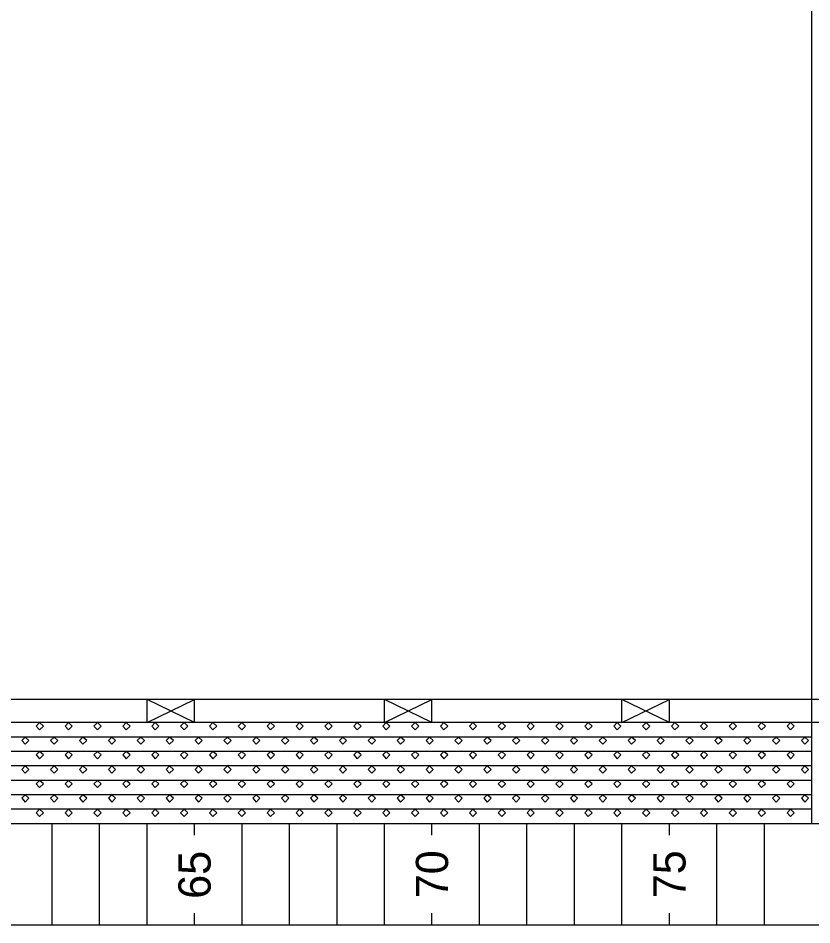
# Model space of a CAD drawing. Extents: x 1313964 to 1316843, y 2087046 to 2096619.
# Drawn here: x 1314005.66 to 1314022.37, y 2089873.43 to 2089892.52 of the extents above; entities that cross this region are included whole.
import ezdxf

# ---------------------------------------------------------------- set-up
doc = ezdxf.new("R2010")
doc.units = 0
doc.layers.add('B-Sub-Contour', color=7, linetype='Continuous')

msp = doc.modelspace()

# ---------------------------------------------------------------- linework, layer by layer
at = {"layer": 'B-Sub-Contour'}
for points in [[(1314036.804, 2089873.434), (1314036.804, 2089916.306), (1313975.385, 2089916.306), (1313975.385, 2089873.434), (1314036.804, 2089873.434)], [(1314022.372, 2089878.178), (1314022.372, 2089894.049)], [(1314034.372, 2089878.178), (1313989.372, 2089878.178)], [(1314008.372, 2089877.691), (1314009.372, 2089878.178)], [(1314009.372, 2089877.691), (1314008.372, 2089878.178)], [(1314008.372, 2089877.691), (1314008.372, 2089878.178)], [(1314009.372, 2089877.691), (1314009.372, 2089878.178)], [(1314013.372, 2089877.691), (1314014.372, 2089878.178)], [(1314014.372, 2089877.691), (1314013.372, 2089878.178)], [(1314013.372, 2089877.691), (1314013.372, 2089878.178)], [(1314014.372, 2089877.691), (1314014.372, 2089878.178)], [(1314018.372, 2089877.691), (1314019.372, 2089878.178)], [(1314019.372, 2089877.691), (1314018.372, 2089878.178)], [(1314018.372, 2089877.691), (1314018.372, 2089878.178)], [(1314019.372, 2089877.691), (1314019.372, 2089878.178)], [(1314022.372, 2089877.691), (1314022.372, 2089878.178)], [(1314034.372, 2089877.691), (1313982.683, 2089877.691)], [(1314022.372, 2089875.563), (1314022.372, 2089877.691)], [(1314022.372, 2089877.387), (1313997.372, 2089877.387)], [(1314022.372, 2089877.083), (1313997.372, 2089877.083)], [(1314022.372, 2089876.779), (1313997.372, 2089876.779)], [(1314022.372, 2089876.475), (1313997.372, 2089876.475)], [(1314022.372, 2089876.171), (1313997.372, 2089876.171)], [(1314022.372, 2089875.867), (1313997.372, 2089875.867)], [(1314034.372, 2089875.563), (1313982.683, 2089875.563)], [(1314006.372, 2089873.434), (1314006.372, 2089875.563)], [(1314006.372, 2089873.434), (1314006.372, 2089875.563)], [(1314007.372, 2089873.434), (1314007.372, 2089875.563)], [(1314008.372, 2089873.434), (1314008.372, 2089875.563)], [(1314008.372, 2089873.434), (1314008.372, 2089875.563)], [(1314009.372, 2089875.319), (1314009.372, 2089875.563)], [(1314010.372, 2089873.434), (1314010.372, 2089875.563)], [(1314010.372, 2089873.434), (1314010.372, 2089875.563)], [(1314011.372, 2089873.434), (1314011.372, 2089875.563)], [(1314012.372, 2089873.434), (1314012.372, 2089875.563)], [(1314012.372, 2089873.434), (1314012.372, 2089875.563)], [(1314013.372, 2089873.434), (1314013.372, 2089875.563)], [(1314014.372, 2089875.319), (1314014.372, 2089875.563)], [(1314014.372, 2089875.319), (1314014.372, 2089875.563)], [(1314015.372, 2089873.434), (1314015.372, 2089875.563)], [(1314016.372, 2089873.434), (1314016.372, 2089875.563)], [(1314016.372, 2089873.434), (1314016.372, 2089875.563)], [(1314017.372, 2089873.434), (1314017.372, 2089875.563)], [(1314018.372, 2089873.434), (1314018.372, 2089875.563)], [(1314018.372, 2089873.434), (1314018.372, 2089875.563)], [(1314019.372, 2089875.319), (1314019.372, 2089875.563)], [(1314020.372, 2089873.434), (1314020.372, 2089875.563)], [(1314020.372, 2089873.434), (1314020.372, 2089875.563)], [(1314021.372, 2089873.434), (1314021.372, 2089875.563)], [(1314009.372, 2089873.434), (1314009.372, 2089873.678)], [(1314014.372, 2089873.434), (1314014.372, 2089873.678)], [(1314014.372, 2089873.434), (1314014.372, 2089873.678)], [(1314019.372, 2089873.434), (1314019.372, 2089873.678)]]:
    msp.add_lwpolyline(points, dxfattribs=at)
for points in [[(1314006.11, 2089877.691), (1314006.037, 2089877.618), (1314006.11, 2089877.539), (1314006.189, 2089877.618)], [(1314006.718, 2089877.691), (1314006.645, 2089877.618), (1314006.718, 2089877.539), (1314006.797, 2089877.618)], [(1314007.326, 2089877.691), (1314007.253, 2089877.618), (1314007.326, 2089877.539), (1314007.405, 2089877.618)], [(1314007.934, 2089877.691), (1314007.862, 2089877.618), (1314007.934, 2089877.539), (1314008.014, 2089877.618)], [(1314008.543, 2089877.691), (1314008.47, 2089877.618), (1314008.543, 2089877.539), (1314008.622, 2089877.618)], [(1314009.151, 2089877.691), (1314009.078, 2089877.618), (1314009.151, 2089877.539), (1314009.23, 2089877.618)], [(1314009.759, 2089877.691), (1314009.686, 2089877.618), (1314009.759, 2089877.539), (1314009.838, 2089877.618)], [(1314010.367, 2089877.691), (1314010.294, 2089877.618), (1314010.367, 2089877.539), (1314010.446, 2089877.618)], [(1314010.975, 2089877.691), (1314010.902, 2089877.618), (1314010.975, 2089877.539), (1314011.054, 2089877.618)], [(1314011.583, 2089877.691), (1314011.51, 2089877.618), (1314011.583, 2089877.539), (1314011.662, 2089877.618)], [(1314012.191, 2089877.691), (1314012.118, 2089877.618), (1314012.191, 2089877.539), (1314012.27, 2089877.618)], [(1314012.799, 2089877.691), (1314012.726, 2089877.618), (1314012.799, 2089877.539), (1314012.878, 2089877.618)], [(1314013.407, 2089877.691), (1314013.334, 2089877.618), (1314013.407, 2089877.539), (1314013.487, 2089877.618)], [(1314014.016, 2089877.691), (1314013.943, 2089877.618), (1314014.016, 2089877.539), (1314014.095, 2089877.618)], [(1314014.624, 2089877.691), (1314014.551, 2089877.618), (1314014.624, 2089877.539), (1314014.703, 2089877.618)], [(1314015.232, 2089877.691), (1314015.159, 2089877.618), (1314015.232, 2089877.539), (1314015.311, 2089877.618)], [(1314015.84, 2089877.691), (1314015.767, 2089877.618), (1314015.84, 2089877.539), (1314015.919, 2089877.618)], [(1314016.448, 2089877.691), (1314016.375, 2089877.618), (1314016.448, 2089877.539), (1314016.527, 2089877.618)], [(1314017.056, 2089877.691), (1314016.983, 2089877.618), (1314017.056, 2089877.539), (1314017.135, 2089877.618)], [(1314017.664, 2089877.691), (1314017.591, 2089877.618), (1314017.664, 2089877.539), (1314017.743, 2089877.618)], [(1314018.272, 2089877.691), (1314018.199, 2089877.618), (1314018.272, 2089877.539), (1314018.351, 2089877.618)], [(1314018.88, 2089877.691), (1314018.807, 2089877.618), (1314018.88, 2089877.539), (1314018.959, 2089877.618)], [(1314019.489, 2089877.691), (1314019.416, 2089877.618), (1314019.489, 2089877.539), (1314019.568, 2089877.618)], [(1314020.097, 2089877.691), (1314020.024, 2089877.618), (1314020.097, 2089877.539), (1314020.176, 2089877.618)], [(1314020.705, 2089877.691), (1314020.632, 2089877.618), (1314020.705, 2089877.539), (1314020.784, 2089877.618)], [(1314021.313, 2089877.691), (1314021.24, 2089877.618), (1314021.313, 2089877.539), (1314021.392, 2089877.618)], [(1314021.921, 2089877.691), (1314021.848, 2089877.618), (1314021.921, 2089877.539), (1314022, 2089877.618)], [(1314005.806, 2089877.387), (1314005.733, 2089877.314), (1314005.806, 2089877.235), (1314005.885, 2089877.314)], [(1314006.414, 2089877.387), (1314006.341, 2089877.314), (1314006.414, 2089877.235), (1314006.493, 2089877.314)], [(1314007.022, 2089877.387), (1314006.949, 2089877.314), (1314007.022, 2089877.235), (1314007.101, 2089877.314)], [(1314007.63, 2089877.387), (1314007.557, 2089877.314), (1314007.63, 2089877.235), (1314007.71, 2089877.314)], [(1314008.239, 2089877.387), (1314008.166, 2089877.314), (1314008.239, 2089877.235), (1314008.318, 2089877.314)], [(1314008.847, 2089877.387), (1314008.774, 2089877.314), (1314008.847, 2089877.235), (1314008.926, 2089877.314)], [(1314009.455, 2089877.387), (1314009.382, 2089877.314), (1314009.455, 2089877.235), (1314009.534, 2089877.314)], [(1314010.063, 2089877.387), (1314009.99, 2089877.314), (1314010.063, 2089877.235), (1314010.142, 2089877.314)], [(1314010.671, 2089877.387), (1314010.598, 2089877.314), (1314010.671, 2089877.235), (1314010.75, 2089877.314)], [(1314011.279, 2089877.387), (1314011.206, 2089877.314), (1314011.279, 2089877.235), (1314011.358, 2089877.314)], [(1314011.887, 2089877.387), (1314011.814, 2089877.314), (1314011.887, 2089877.235), (1314011.966, 2089877.314)], [(1314012.495, 2089877.387), (1314012.422, 2089877.314), (1314012.495, 2089877.235), (1314012.574, 2089877.314)], [(1314013.103, 2089877.387), (1314013.03, 2089877.314), (1314013.103, 2089877.235), (1314013.182, 2089877.314)], [(1314013.712, 2089877.387), (1314013.639, 2089877.314), (1314013.712, 2089877.235), (1314013.791, 2089877.314)], [(1314014.32, 2089877.387), (1314014.247, 2089877.314), (1314014.32, 2089877.235), (1314014.399, 2089877.314)], [(1314014.928, 2089877.387), (1314014.855, 2089877.314), (1314014.928, 2089877.235), (1314015.007, 2089877.314)], [(1314015.536, 2089877.387), (1314015.463, 2089877.314), (1314015.536, 2089877.235), (1314015.615, 2089877.314)], [(1314016.144, 2089877.387), (1314016.071, 2089877.314), (1314016.144, 2089877.235), (1314016.223, 2089877.314)], [(1314016.752, 2089877.387), (1314016.679, 2089877.314), (1314016.752, 2089877.235), (1314016.831, 2089877.314)], [(1314017.36, 2089877.387), (1314017.287, 2089877.314), (1314017.36, 2089877.235), (1314017.439, 2089877.314)], [(1314017.968, 2089877.387), (1314017.895, 2089877.314), (1314017.968, 2089877.235), (1314018.047, 2089877.314)], [(1314018.576, 2089877.387), (1314018.503, 2089877.314), (1314018.576, 2089877.235), (1314018.655, 2089877.314)], [(1314019.184, 2089877.387), (1314019.112, 2089877.314), (1314019.184, 2089877.235), (1314019.264, 2089877.314)], [(1314019.793, 2089877.387), (1314019.72, 2089877.314), (1314019.793, 2089877.235), (1314019.872, 2089877.314)], [(1314020.401, 2089877.387), (1314020.328, 2089877.314), (1314020.401, 2089877.235), (1314020.48, 2089877.314)], [(1314021.009, 2089877.387), (1314020.936, 2089877.314), (1314021.009, 2089877.235), (1314021.088, 2089877.314)], [(1314021.617, 2089877.387), (1314021.544, 2089877.314), (1314021.617, 2089877.235), (1314021.696, 2089877.314)], [(1314022.225, 2089877.387), (1314022.152, 2089877.314), (1314022.225, 2089877.235), (1314022.304, 2089877.314)], [(1314006.11, 2089877.083), (1314006.037, 2089877.01), (1314006.11, 2089876.931), (1314006.189, 2089877.01)], [(1314006.718, 2089877.083), (1314006.645, 2089877.01), (1314006.718, 2089876.931), (1314006.797, 2089877.01)], [(1314007.326, 2089877.083), (1314007.253, 2089877.01), (1314007.326, 2089876.931), (1314007.405, 2089877.01)], [(1314007.934, 2089877.083), (1314007.862, 2089877.01), (1314007.934, 2089876.931), (1314008.014, 2089877.01)], [(1314008.543, 2089877.083), (1314008.47, 2089877.01), (1314008.543, 2089876.931), (1314008.622, 2089877.01)], [(1314009.151, 2089877.083), (1314009.078, 2089877.01), (1314009.151, 2089876.931), (1314009.23, 2089877.01)], [(1314009.759, 2089877.083), (1314009.686, 2089877.01), (1314009.759, 2089876.931), (1314009.838, 2089877.01)], [(1314010.367, 2089877.083), (1314010.294, 2089877.01), (1314010.367, 2089876.931), (1314010.446, 2089877.01)], [(1314010.975, 2089877.083), (1314010.902, 2089877.01), (1314010.975, 2089876.931), (1314011.054, 2089877.01)], [(1314011.583, 2089877.083), (1314011.51, 2089877.01), (1314011.583, 2089876.931), (1314011.662, 2089877.01)], [(1314012.191, 2089877.083), (1314012.118, 2089877.01), (1314012.191, 2089876.931), (1314012.27, 2089877.01)], [(1314012.799, 2089877.083), (1314012.726, 2089877.01), (1314012.799, 2089876.931), (1314012.878, 2089877.01)], [(1314013.407, 2089877.083), (1314013.334, 2089877.01), (1314013.407, 2089876.931), (1314013.487, 2089877.01)], [(1314014.016, 2089877.083), (1314013.943, 2089877.01), (1314014.016, 2089876.931), (1314014.095, 2089877.01)], [(1314014.624, 2089877.083), (1314014.551, 2089877.01), (1314014.624, 2089876.931), (1314014.703, 2089877.01)], [(1314015.232, 2089877.083), (1314015.159, 2089877.01), (1314015.232, 2089876.931), (1314015.311, 2089877.01)], [(1314015.84, 2089877.083), (1314015.767, 2089877.01), (1314015.84, 2089876.931), (1314015.919, 2089877.01)], [(1314016.448, 2089877.083), (1314016.375, 2089877.01), (1314016.448, 2089876.931), (1314016.527, 2089877.01)], [(1314017.056, 2089877.083), (1314016.983, 2089877.01), (1314017.056, 2089876.931), (1314017.135, 2089877.01)], [(1314017.664, 2089877.083), (1314017.591, 2089877.01), (1314017.664, 2089876.931), (1314017.743, 2089877.01)], [(1314018.272, 2089877.083), (1314018.199, 2089877.01), (1314018.272, 2089876.931), (1314018.351, 2089877.01)], [(1314018.88, 2089877.083), (1314018.807, 2089877.01), (1314018.88, 2089876.931), (1314018.959, 2089877.01)], [(1314019.489, 2089877.083), (1314019.416, 2089877.01), (1314019.489, 2089876.931), (1314019.568, 2089877.01)], [(1314020.097, 2089877.083), (1314020.024, 2089877.01), (1314020.097, 2089876.931), (1314020.176, 2089877.01)], [(1314020.705, 2089877.083), (1314020.632, 2089877.01), (1314020.705, 2089876.931), (1314020.784, 2089877.01)], [(1314021.313, 2089877.083), (1314021.24, 2089877.01), (1314021.313, 2089876.931), (1314021.392, 2089877.01)], [(1314021.921, 2089877.083), (1314021.848, 2089877.01), (1314021.921, 2089876.931), (1314022, 2089877.01)], [(1314005.806, 2089876.779), (1314005.733, 2089876.706), (1314005.806, 2089876.627), (1314005.885, 2089876.706)], [(1314006.414, 2089876.779), (1314006.341, 2089876.706), (1314006.414, 2089876.627), (1314006.493, 2089876.706)], [(1314007.022, 2089876.779), (1314006.949, 2089876.706), (1314007.022, 2089876.627), (1314007.101, 2089876.706)], [(1314007.63, 2089876.779), (1314007.557, 2089876.706), (1314007.63, 2089876.627), (1314007.71, 2089876.706)], [(1314008.239, 2089876.779), (1314008.166, 2089876.706), (1314008.239, 2089876.627), (1314008.318, 2089876.706)], [(1314008.847, 2089876.779), (1314008.774, 2089876.706), (1314008.847, 2089876.627), (1314008.926, 2089876.706)], [(1314009.455, 2089876.779), (1314009.382, 2089876.706), (1314009.455, 2089876.627), (1314009.534, 2089876.706)], [(1314010.063, 2089876.779), (1314009.99, 2089876.706), (1314010.063, 2089876.627), (1314010.142, 2089876.706)], [(1314010.671, 2089876.779), (1314010.598, 2089876.706), (1314010.671, 2089876.627), (1314010.75, 2089876.706)], [(1314011.279, 2089876.779), (1314011.206, 2089876.706), (1314011.279, 2089876.627), (1314011.358, 2089876.706)], [(1314011.887, 2089876.779), (1314011.814, 2089876.706), (1314011.887, 2089876.627), (1314011.966, 2089876.706)], [(1314012.495, 2089876.779), (1314012.422, 2089876.706), (1314012.495, 2089876.627), (1314012.574, 2089876.706)], [(1314013.103, 2089876.779), (1314013.03, 2089876.706), (1314013.103, 2089876.627), (1314013.182, 2089876.706)], [(1314013.712, 2089876.779), (1314013.639, 2089876.706), (1314013.712, 2089876.627), (1314013.791, 2089876.706)], [(1314014.32, 2089876.779), (1314014.247, 2089876.706), (1314014.32, 2089876.627), (1314014.399, 2089876.706)], [(1314014.928, 2089876.779), (1314014.855, 2089876.706), (1314014.928, 2089876.627), (1314015.007, 2089876.706)], [(1314015.536, 2089876.779), (1314015.463, 2089876.706), (1314015.536, 2089876.627), (1314015.615, 2089876.706)], [(1314016.144, 2089876.779), (1314016.071, 2089876.706), (1314016.144, 2089876.627), (1314016.223, 2089876.706)], [(1314016.752, 2089876.779), (1314016.679, 2089876.706), (1314016.752, 2089876.627), (1314016.831, 2089876.706)], [(1314017.36, 2089876.779), (1314017.287, 2089876.706), (1314017.36, 2089876.627), (1314017.439, 2089876.706)], [(1314017.968, 2089876.779), (1314017.895, 2089876.706), (1314017.968, 2089876.627), (1314018.047, 2089876.706)], [(1314018.576, 2089876.779), (1314018.503, 2089876.706), (1314018.576, 2089876.627), (1314018.655, 2089876.706)], [(1314019.184, 2089876.779), (1314019.112, 2089876.706), (1314019.184, 2089876.627), (1314019.264, 2089876.706)], [(1314019.793, 2089876.779), (1314019.72, 2089876.706), (1314019.793, 2089876.627), (1314019.872, 2089876.706)], [(1314020.401, 2089876.779), (1314020.328, 2089876.706), (1314020.401, 2089876.627), (1314020.48, 2089876.706)], [(1314021.009, 2089876.779), (1314020.936, 2089876.706), (1314021.009, 2089876.627), (1314021.088, 2089876.706)], [(1314021.617, 2089876.779), (1314021.544, 2089876.706), (1314021.617, 2089876.627), (1314021.696, 2089876.706)], [(1314022.225, 2089876.779), (1314022.152, 2089876.706), (1314022.225, 2089876.627), (1314022.304, 2089876.706)], [(1314006.11, 2089876.475), (1314006.037, 2089876.402), (1314006.11, 2089876.323), (1314006.189, 2089876.402)], [(1314006.718, 2089876.475), (1314006.645, 2089876.402), (1314006.718, 2089876.323), (1314006.797, 2089876.402)], [(1314007.326, 2089876.475), (1314007.253, 2089876.402), (1314007.326, 2089876.323), (1314007.405, 2089876.402)], [(1314007.934, 2089876.475), (1314007.862, 2089876.402), (1314007.934, 2089876.323), (1314008.014, 2089876.402)], [(1314008.543, 2089876.475), (1314008.47, 2089876.402), (1314008.543, 2089876.323), (1314008.622, 2089876.402)], [(1314009.151, 2089876.475), (1314009.078, 2089876.402), (1314009.151, 2089876.323), (1314009.23, 2089876.402)], [(1314009.759, 2089876.475), (1314009.686, 2089876.402), (1314009.759, 2089876.323), (1314009.838, 2089876.402)], [(1314010.367, 2089876.475), (1314010.294, 2089876.402), (1314010.367, 2089876.323), (1314010.446, 2089876.402)], [(1314010.975, 2089876.475), (1314010.902, 2089876.402), (1314010.975, 2089876.323), (1314011.054, 2089876.402)], [(1314011.583, 2089876.475), (1314011.51, 2089876.402), (1314011.583, 2089876.323), (1314011.662, 2089876.402)], [(1314012.191, 2089876.475), (1314012.118, 2089876.402), (1314012.191, 2089876.323), (1314012.27, 2089876.402)], [(1314012.799, 2089876.475), (1314012.726, 2089876.402), (1314012.799, 2089876.323), (1314012.878, 2089876.402)], [(1314013.407, 2089876.475), (1314013.334, 2089876.402), (1314013.407, 2089876.323), (1314013.487, 2089876.402)], [(1314014.016, 2089876.475), (1314013.943, 2089876.402), (1314014.016, 2089876.323), (1314014.095, 2089876.402)], [(1314014.624, 2089876.475), (1314014.551, 2089876.402), (1314014.624, 2089876.323), (1314014.703, 2089876.402)], [(1314015.232, 2089876.475), (1314015.159, 2089876.402), (1314015.232, 2089876.323), (1314015.311, 2089876.402)], [(1314015.84, 2089876.475), (1314015.767, 2089876.402), (1314015.84, 2089876.323), (1314015.919, 2089876.402)], [(1314016.448, 2089876.475), (1314016.375, 2089876.402), (1314016.448, 2089876.323), (1314016.527, 2089876.402)], [(1314017.056, 2089876.475), (1314016.983, 2089876.402), (1314017.056, 2089876.323), (1314017.135, 2089876.402)], [(1314017.664, 2089876.475), (1314017.591, 2089876.402), (1314017.664, 2089876.323), (1314017.743, 2089876.402)], [(1314018.272, 2089876.475), (1314018.199, 2089876.402), (1314018.272, 2089876.323), (1314018.351, 2089876.402)], [(1314018.88, 2089876.475), (1314018.807, 2089876.402), (1314018.88, 2089876.323), (1314018.959, 2089876.402)], [(1314019.489, 2089876.475), (1314019.416, 2089876.402), (1314019.489, 2089876.323), (1314019.568, 2089876.402)], [(1314020.097, 2089876.475), (1314020.024, 2089876.402), (1314020.097, 2089876.323), (1314020.176, 2089876.402)], [(1314020.705, 2089876.475), (1314020.632, 2089876.402), (1314020.705, 2089876.323), (1314020.784, 2089876.402)], [(1314021.313, 2089876.475), (1314021.24, 2089876.402), (1314021.313, 2089876.323), (1314021.392, 2089876.402)], [(1314021.921, 2089876.475), (1314021.848, 2089876.402), (1314021.921, 2089876.323), (1314022, 2089876.402)], [(1314005.806, 2089876.171), (1314005.733, 2089876.098), (1314005.806, 2089876.019), (1314005.885, 2089876.098)], [(1314006.414, 2089876.171), (1314006.341, 2089876.098), (1314006.414, 2089876.019), (1314006.493, 2089876.098)], [(1314007.022, 2089876.171), (1314006.949, 2089876.098), (1314007.022, 2089876.019), (1314007.101, 2089876.098)], [(1314007.63, 2089876.171), (1314007.557, 2089876.098), (1314007.63, 2089876.019), (1314007.71, 2089876.098)], [(1314008.239, 2089876.171), (1314008.166, 2089876.098), (1314008.239, 2089876.019), (1314008.318, 2089876.098)], [(1314008.847, 2089876.171), (1314008.774, 2089876.098), (1314008.847, 2089876.019), (1314008.926, 2089876.098)], [(1314009.455, 2089876.171), (1314009.382, 2089876.098), (1314009.455, 2089876.019), (1314009.534, 2089876.098)], [(1314010.063, 2089876.171), (1314009.99, 2089876.098), (1314010.063, 2089876.019), (1314010.142, 2089876.098)], [(1314010.671, 2089876.171), (1314010.598, 2089876.098), (1314010.671, 2089876.019), (1314010.75, 2089876.098)], [(1314011.279, 2089876.171), (1314011.206, 2089876.098), (1314011.279, 2089876.019), (1314011.358, 2089876.098)], [(1314011.887, 2089876.171), (1314011.814, 2089876.098), (1314011.887, 2089876.019), (1314011.966, 2089876.098)], [(1314012.495, 2089876.171), (1314012.422, 2089876.098), (1314012.495, 2089876.019), (1314012.574, 2089876.098)], [(1314013.103, 2089876.171), (1314013.03, 2089876.098), (1314013.103, 2089876.019), (1314013.182, 2089876.098)], [(1314013.712, 2089876.171), (1314013.639, 2089876.098), (1314013.712, 2089876.019), (1314013.791, 2089876.098)], [(1314014.32, 2089876.171), (1314014.247, 2089876.098), (1314014.32, 2089876.019), (1314014.399, 2089876.098)], [(1314014.928, 2089876.171), (1314014.855, 2089876.098), (1314014.928, 2089876.019), (1314015.007, 2089876.098)], [(1314015.536, 2089876.171), (1314015.463, 2089876.098), (1314015.536, 2089876.019), (1314015.615, 2089876.098)], [(1314016.144, 2089876.171), (1314016.071, 2089876.098), (1314016.144, 2089876.019), (1314016.223, 2089876.098)], [(1314016.752, 2089876.171), (1314016.679, 2089876.098), (1314016.752, 2089876.019), (1314016.831, 2089876.098)], [(1314017.36, 2089876.171), (1314017.287, 2089876.098), (1314017.36, 2089876.019), (1314017.439, 2089876.098)], [(1314017.968, 2089876.171), (1314017.895, 2089876.098), (1314017.968, 2089876.019), (1314018.047, 2089876.098)], [(1314018.576, 2089876.171), (1314018.503, 2089876.098), (1314018.576, 2089876.019), (1314018.655, 2089876.098)], [(1314019.184, 2089876.171), (1314019.112, 2089876.098), (1314019.184, 2089876.019), (1314019.264, 2089876.098)], [(1314019.793, 2089876.171), (1314019.72, 2089876.098), (1314019.793, 2089876.019), (1314019.872, 2089876.098)], [(1314020.401, 2089876.171), (1314020.328, 2089876.098), (1314020.401, 2089876.019), (1314020.48, 2089876.098)], [(1314021.009, 2089876.171), (1314020.936, 2089876.098), (1314021.009, 2089876.019), (1314021.088, 2089876.098)], [(1314021.617, 2089876.171), (1314021.544, 2089876.098), (1314021.617, 2089876.019), (1314021.696, 2089876.098)], [(1314022.225, 2089876.171), (1314022.152, 2089876.098), (1314022.225, 2089876.019), (1314022.304, 2089876.098)], [(1314006.11, 2089875.867), (1314006.037, 2089875.794), (1314006.11, 2089875.715), (1314006.189, 2089875.794)], [(1314006.718, 2089875.867), (1314006.645, 2089875.794), (1314006.718, 2089875.715), (1314006.797, 2089875.794)], [(1314007.326, 2089875.867), (1314007.253, 2089875.794), (1314007.326, 2089875.715), (1314007.405, 2089875.794)], [(1314007.934, 2089875.867), (1314007.862, 2089875.794), (1314007.934, 2089875.715), (1314008.014, 2089875.794)], [(1314008.543, 2089875.867), (1314008.47, 2089875.794), (1314008.543, 2089875.715), (1314008.622, 2089875.794)], [(1314009.151, 2089875.867), (1314009.078, 2089875.794), (1314009.151, 2089875.715), (1314009.23, 2089875.794)], [(1314009.759, 2089875.867), (1314009.686, 2089875.794), (1314009.759, 2089875.715), (1314009.838, 2089875.794)], [(1314010.367, 2089875.867), (1314010.294, 2089875.794), (1314010.367, 2089875.715), (1314010.446, 2089875.794)], [(1314010.975, 2089875.867), (1314010.902, 2089875.794), (1314010.975, 2089875.715), (1314011.054, 2089875.794)], [(1314011.583, 2089875.867), (1314011.51, 2089875.794), (1314011.583, 2089875.715), (1314011.662, 2089875.794)], [(1314012.191, 2089875.867), (1314012.118, 2089875.794), (1314012.191, 2089875.715), (1314012.27, 2089875.794)], [(1314012.799, 2089875.867), (1314012.726, 2089875.794), (1314012.799, 2089875.715), (1314012.878, 2089875.794)], [(1314013.407, 2089875.867), (1314013.334, 2089875.794), (1314013.407, 2089875.715), (1314013.487, 2089875.794)], [(1314014.016, 2089875.867), (1314013.943, 2089875.794), (1314014.016, 2089875.715), (1314014.095, 2089875.794)], [(1314014.624, 2089875.867), (1314014.551, 2089875.794), (1314014.624, 2089875.715), (1314014.703, 2089875.794)], [(1314015.232, 2089875.867), (1314015.159, 2089875.794), (1314015.232, 2089875.715), (1314015.311, 2089875.794)], [(1314015.84, 2089875.867), (1314015.767, 2089875.794), (1314015.84, 2089875.715), (1314015.919, 2089875.794)], [(1314016.448, 2089875.867), (1314016.375, 2089875.794), (1314016.448, 2089875.715), (1314016.527, 2089875.794)], [(1314017.056, 2089875.867), (1314016.983, 2089875.794), (1314017.056, 2089875.715), (1314017.135, 2089875.794)], [(1314017.664, 2089875.867), (1314017.591, 2089875.794), (1314017.664, 2089875.715), (1314017.743, 2089875.794)], [(1314018.272, 2089875.867), (1314018.199, 2089875.794), (1314018.272, 2089875.715), (1314018.351, 2089875.794)], [(1314018.88, 2089875.867), (1314018.807, 2089875.794), (1314018.88, 2089875.715), (1314018.959, 2089875.794)], [(1314019.489, 2089875.867), (1314019.416, 2089875.794), (1314019.489, 2089875.715), (1314019.568, 2089875.794)], [(1314020.097, 2089875.867), (1314020.024, 2089875.794), (1314020.097, 2089875.715), (1314020.176, 2089875.794)], [(1314020.705, 2089875.867), (1314020.632, 2089875.794), (1314020.705, 2089875.715), (1314020.784, 2089875.794)], [(1314021.313, 2089875.867), (1314021.24, 2089875.794), (1314021.313, 2089875.715), (1314021.392, 2089875.794)], [(1314021.921, 2089875.867), (1314021.848, 2089875.794), (1314021.921, 2089875.715), (1314022, 2089875.794)]]:
    msp.add_lwpolyline(points, close=True, dxfattribs=at)

# ---------------------------------------------------------------- texts
for s, p in [('65', (1314009.711, 2089873.982)), ('70', (1314014.711, 2089873.994)), ('70', (1314014.711, 2089873.994)), ('75', (1314019.711, 2089873.994))]:
    msp.add_text(s, height=0.6786, rotation=90, dxfattribs=at).set_placement(p)

doc.saveas('drawing.dxf')
